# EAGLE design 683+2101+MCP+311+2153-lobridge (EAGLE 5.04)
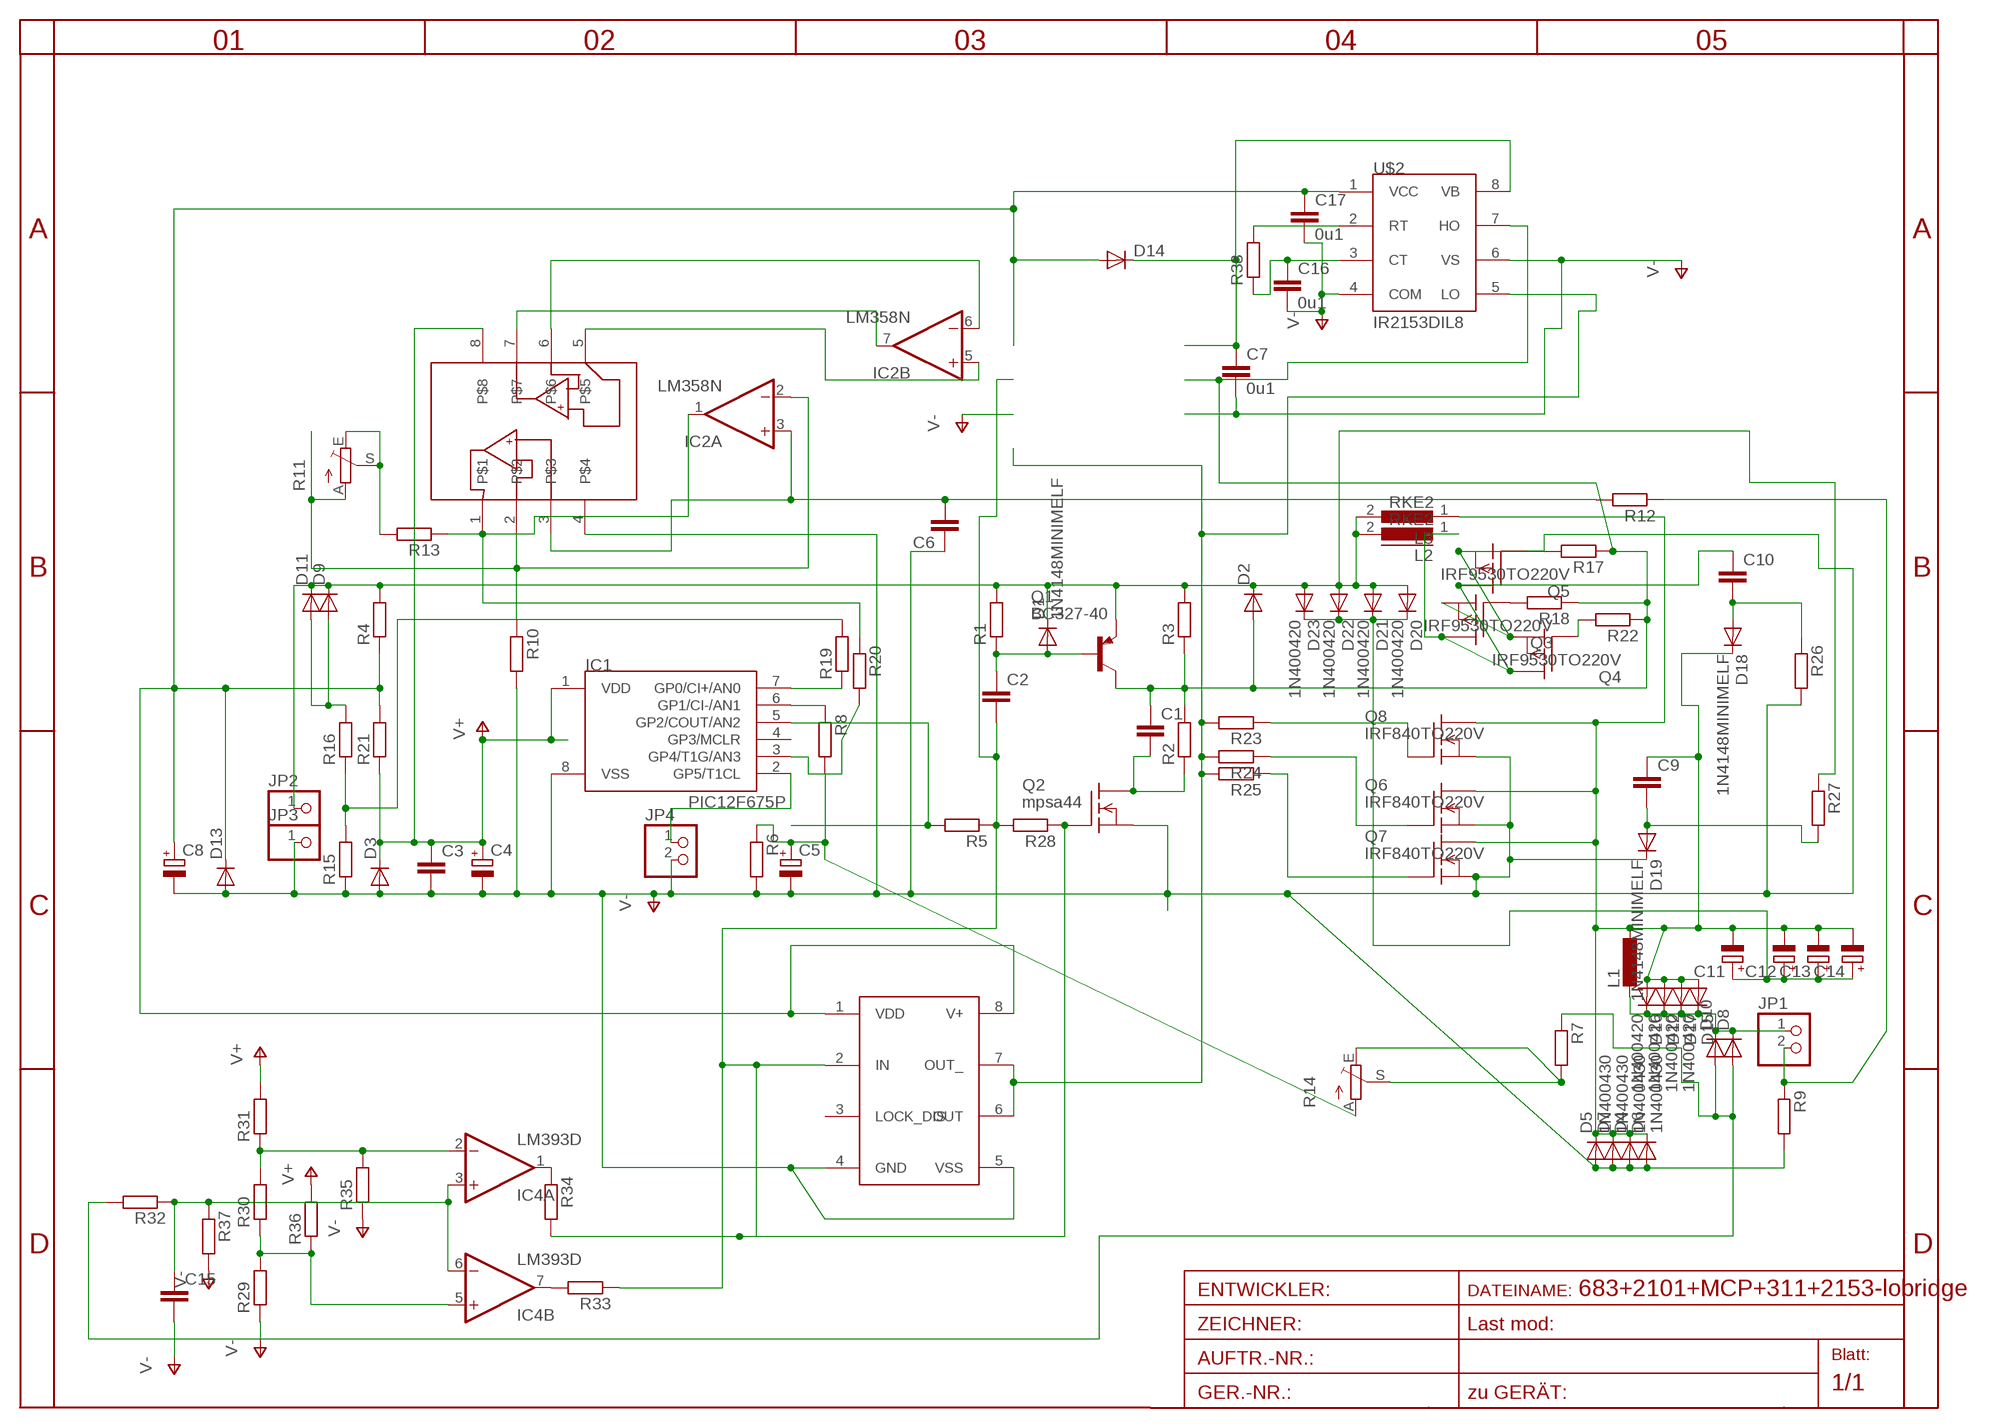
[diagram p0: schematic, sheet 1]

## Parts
C1  C-EU225-074X268  [C225-074X268]
C2  C-EU225-062X268  [C225-062X268]
C3  C-EU050-025X075  [C050-025X075]
C4  CPOL-EUE2.5-7  [E2,5-7]
C5  CPOL-EU5-13  [2,5-5-FLAT]
C6  C-EU025_050-025X075  [C025_050-025X075]
C7  0u1  C-EU050-025X075  [C050-025X075]
C8  CPOL-EU5-13  [2,5-5-FLAT]
C9  C-EUC1812  [C1812]
C10  C-EUC1812K  [C1812K]
C11  CPOL-EUSANYO_SMD_E7  [SANYO-OSCON_SMD_E7]
C12  CPOL-EUSANYO_SMD_E7  [SANYO-OSCON_SMD_E7]
C13  CPOL-EUSANYO_SMD_E7  [SANYO-OSCON_SMD_E7]
C14  CPOL-EUSANYO_SMD_E7  [SANYO-OSCON_SMD_E7]
C15  C-EU025-025X050  [C025-025X050]
C16  0u1  C-EU025-050X050  [C025-050X050]
C17  0u1  C-EU050-030X075  [C050-030X075]
D1  1N4148MINIMELF  [MINIMELF]
D2  DIODE-D-5  [D-5]
D3  DIODE-D-2.5  [D-2.5]
D4  1N400430  [DO41-30]
D5  1N400430  [DO41-30]
D6  1N400430  [DO41-30]
D7  1N400430  [DO41-30]
D8  DIODE-D-2.5  [D-2.5]
D9  DIODE-D-2.5  [D-2.5]
D10  DIODE-DO41-30  [DO41-30]
D11  DIODE-D-10  [D-10]
D12  1N400420  [DO41-20]
D13  DIODE-D-2.5  [D-2.5]
D14  DIODE-D-5  [D-5]
D15  1N400420  [DO41-20]
D16  1N400420  [DO41-20]
D17  1N400420  [DO41-20]
D18  1N4148MINIMELF  [MINIMELF]
D19  1N4148MINIMELF  [MINIMELF]
D20  1N400420  [DO41-20]
D21  1N400420  [DO41-20]
D22  1N400420  [DO41-20]
D23  1N400420  [DO41-20]
IC1  PIC12F675P  [DIL8]
IC2  LM358N  [DIL08]
IC3  TC4432X  [SO-08]
IC4  LM393D  [SO08]
JP1  PINHD-1X2  [1X02]
JP2  PINHD-1X1  [1X01]
JP3  PINHD-1X1  [1X01]
JP4  PINHD-1X2  [1X02]
L1  L-EU0204/7  [0204/7]
L2  RKE2  [RKE2]
L3  RKE2  [RKE2]
Q1  BC327-40  [TO92-EBC]
Q2  mpsa44  TN0604N3  [TO-92]
Q3  IRF9530TO220V  [TO220V]
Q4  IRF9530TO220V  [TO220V]
Q5  IRF9530TO220V  [TO220V]
Q6  IRF840TO220V  [TO220V]
Q7  IRF840TO220V  [TO220V]
Q8  IRF840TO220V  [TO220V]
R1  R-EU_0204/2V  [0204V]
R2  R-EU_0207/25  [0207/25]
R3  R-EU_0204/2V  [0204V]
R4  R-EU_0207/10  [0207/10]
R5  R-EU_0207/40  [0207/40]
R6  R-EU_0207/10  [0207/10]
R7  R-EU_0207/15  [0207/15]
R8  R-EU_0207/10  [0207/10]
R9  R-EU_0207/10  [0207/10]
R10  R-EU_0207/15  [0207/15]
R11  TRIM_EU-CIP20C-4MM  [CIP20C-4MM]
R12  R-EU_0207/30  [0207/30]
R13  R-EU_0207/40  [0207/40]
R14  TRIM_EU-CIP20C-4MM  [CIP20C-4MM]
R15  R-EU_0204/5  [0204/5]
R16  R-EU_0207/25  [0207/25]
R17  R-EU_R1206  [R1206]
R18  R-EU_R1206  [R1206]
R19  R-EU_0204/5  [0204/5]
R20  R-EU_0204/5  [0204/5]
R21  R-EU_0207/10  [0207/10]
R22  R-EU_R1206  [R1206]
R23  R-EU_R1206  [R1206]
R24  R-EU_R1206  [R1206]
R25  R-EU_R1206  [R1206]
R26  R-EU_0207/25  [0207/25]
R27  R-EU_0207/30  [0207/30]
R28  R-EU_R0805  [R0805]
R29  R-EU_0204/5  [0204/5]
R30  R-EU_0204/5  [0204/5]
R31  R-EU_0204/5  [0204/5]
R32  R-EU_0207/40  [0207/40]
R33  R-EU_0207/12  [0207/12]
R34  R-EU_0207/20  [0207/20]
R35  R-EU_0204/5  [0204/5]
R36  R-EU_0204/5  [0204/5]
R37  R-EU_0204/5  [0204/5]
R38  R-EU_0204/2V  [0204V]
U$1  MCP6042SOIC  [SO-08]
U$2  IR2153DIL8  [DIL08]

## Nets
BB: C2.2 IC3.2(IN) Q2.2(G) R5.1 R28.1 R28.2 R33.1 R34.2
CT: C16.1 R38.1 U$2.3(CT)
DRAIN: C9.1 C11.- C12.- C13.- C14.- D4.C D5.C D6.C D7.C D12.A D15.A D16.A D17.A D18.C L1.1 L3.1 Q6.2(D) Q7.2(D) Q8.2(D)
GATE: C1.1 D2.A Q1.C R2.2 R3.1 R17.1 R18.1 R22.1 U$2.7(HO)
MPOINT: C5.+ R6.1 R8.2 R14.A
N$1: C1.2 Q2.3(D) R2.1
N$2: IC2.6(B:-IN) U$1.6
N$3: IC1.5(GP2/COUT/AN2) R5.2
N$4: Q3.1(G) R18.2
N$5: IC1.6(GP1/CI-/AN1) R8.1
N$6: IC2.2(A:-IN) R10.1 R11.A U$1.2
N$7: IC2.1(A:OUT) R13.1 R20.1 U$1.1
N$9: C6.2 IC2.3(A:+IN) R12.2 U$1.3
N$10: R7.2 R14.E R14.S
N$11: Q5.1(G) R17.2
N$12: R15.2 R16.1 R19.2
N$13: D9.A D11.A R16.2
N$14: IC1.7(GP0/CI+/AN0) R19.1
N$15: IC1.2(GP5/T1CL) JP4.1
N$16: D8.A D10.A R7.1 R32.2
N$17: IC1.3(GP4/T1G/AN3) R20.2
N$18: IC2.5(B:+IN) U$1.5
N$19: C15.1 IC4.3(A:+IN) IC4.6(B:-IN) R32.1 R37.1
N$20: IC2.7(B:OUT) U$1.7
N$21: C10.1 L2.1 Q3.2(D) Q4.2(D) Q5.2(D)
N$22: IC4.7(B:OUT) R33.2
N$23: Q4.1(G) R22.2
N$24: C10.2 D18.A R26.1
N$25: Q7.1(G) R25.1
N$26: Q6.1(G) R24.1
N$27: Q8.1(G) R23.1
N$28: C9.2 D19.A R27.2
N$29: R11.E R11.S R13.2
N$30: IC4.1(A:OUT) R34.1
N$31: C11.+ C12.+ C13.+ C14.+ D20.C D21.C D22.C D23.C
N$32: IC4.5(B:+IN) R29.2 R30.1 R36.1
N$33: IC3.6(OUT) IC3.7(OUT_) R23.2 R24.2 R25.2 U$2.5(LO)
N$34: IC4.2(A:-IN) R30.2 R31.1 R35.2
N$40: R38.2 U$2.2(RT)
OUT+: D8.C D10.C D12.C D15.C D16.C D17.C JP1.1 L1.2
OUT-: JP1.2 R9.1 R12.1
TB: C2.1 D1.A Q1.B R1.1
V+: C3.1 C4.+ D3.C IC1.1(VDD) R21.1 R31.2 R36.2 U$1.8
V-: C3.2 C4.- C5.- C6.1 C7.2 C8.- C15.2 C16.2 C17.2 D3.A D4.A D5.A D6.A D7.A D13.A D19.C IC1.8(VSS) IC3.4(GND) IC3.5(VSS) JP3.1 JP4.2 Q2.1(S) Q3.3(S) Q4.3(S) Q5.3(S) Q6.3(S) Q7.3(S) Q8.3(S) R6.2 R9.2 R10.2 R15.1 R26.2 R29.1 R35.1 R37.2 U$1.4 U$2.4(COM) U$2.6(VS)
VB: C7.1 D14.C U$2.8(VB)
VCC: C8.+ C17.1 D13.C D14.A IC3.1(VDD) IC3.8(V+) R4.1 R21.2 U$2.1(VCC)
VIN: D1.C D2.C D9.C D11.C D20.A D21.A D22.A D23.A JP2.1 L2.2 L3.2 Q1.E R1.2 R3.2 R4.2 R27.1
Unconnected: IC1.4(GP3/MCLR) IC3.3(LOCK_DIS)

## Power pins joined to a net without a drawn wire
V+: IC2.8(P:V+) IC4.8(P:V+)
V-: IC2.4(P:V-) IC4.4(P:V-)

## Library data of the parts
C1-C3 C6 C7 C9 C10 C15-C17 = rcl-2:C-EU: CAPACITOR, European symbol
C4 C5 C8 C11-C14 = rcl-2:CPOL-EU: POLARIZED CAPACITOR, European symbol
D1 D18 D19 = diode-1:1N4148: DIODE
D2 D3 D8-D11 D13 D14 = diode-1:DIODE-: DIODE
D4-D7 D12 D15-D17 D20-D23 = diode-1:1N4004: DIODE
IC1 = microchip-5:PIC12F6*: uPC nW 1k Program Flash memory 2x Timer Comparator 10b A/D converter/ 4xIN
IC2 = linear:LM358: OP AMP also LM158; LM258; LM2904 Source: http://cache.national.com/ds/LM/LM158.pdf
IC3 = microchip:TC4432
IC4 = linear:LM393: COMPARATOR
JP1 JP4 = pinhead:PINHD-1X2: PIN HEADER
JP2 JP3 = pinhead:PINHD-1X1: PIN HEADER
L1 = rcl-2:L-EU: INDUCTOR, European symbol
L2 L3 = inductors:RKE2: INDUCTOR
Q1 = transistor-pnp:BC327*: PNP Transistror
Q2 = transistor-fet:TN0604N3: N-Channel Enhancement MOSFET 40V; 4A; 0,75Ohm
Q3-Q5 = transistor-fet:IRF9530: P-Channel Enhancement MOSFET (HEXFET); -100V; -12A; 0,3Ohm
Q6-Q8 = transistor-fet:IRF840: N-Channel Enhancement MOSFET (HEXFET); 500V; 8A; 0,85Ohm
R1-R10 R12 R13 R15-R38 = rcl-2:R-EU_: RESISTOR, European symbol
R11 R14 = pot:TRIM_EU-: POTENTIOMETER
U$1 = microchip-3:MCP6042
U$2 = irf-2:IR2153

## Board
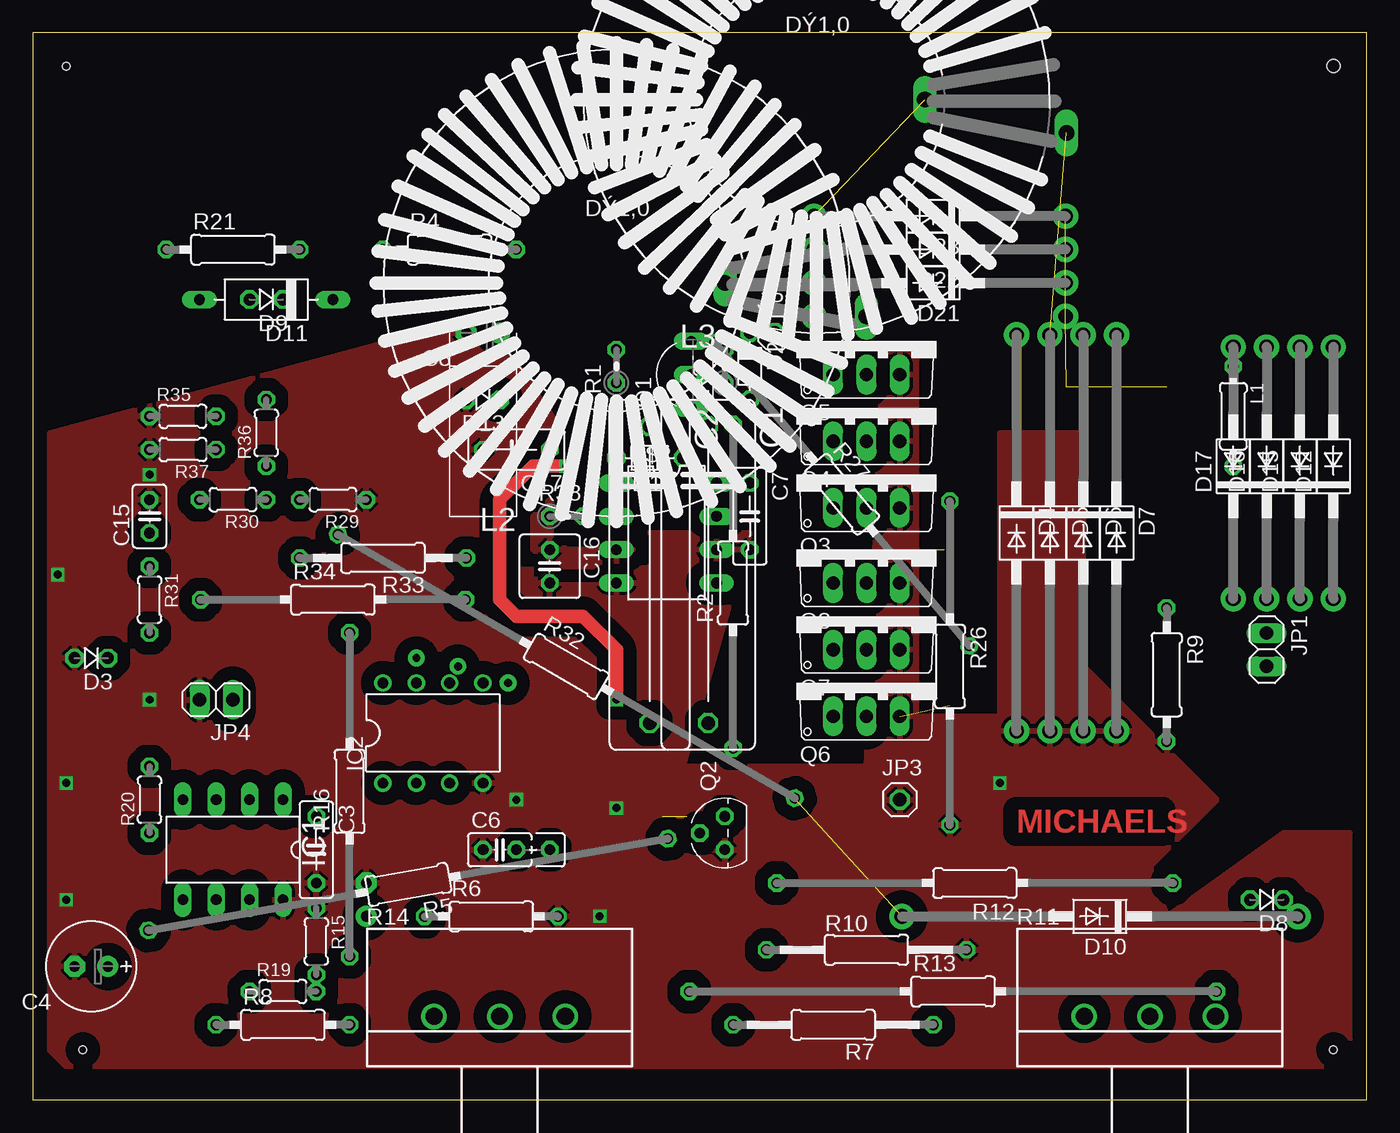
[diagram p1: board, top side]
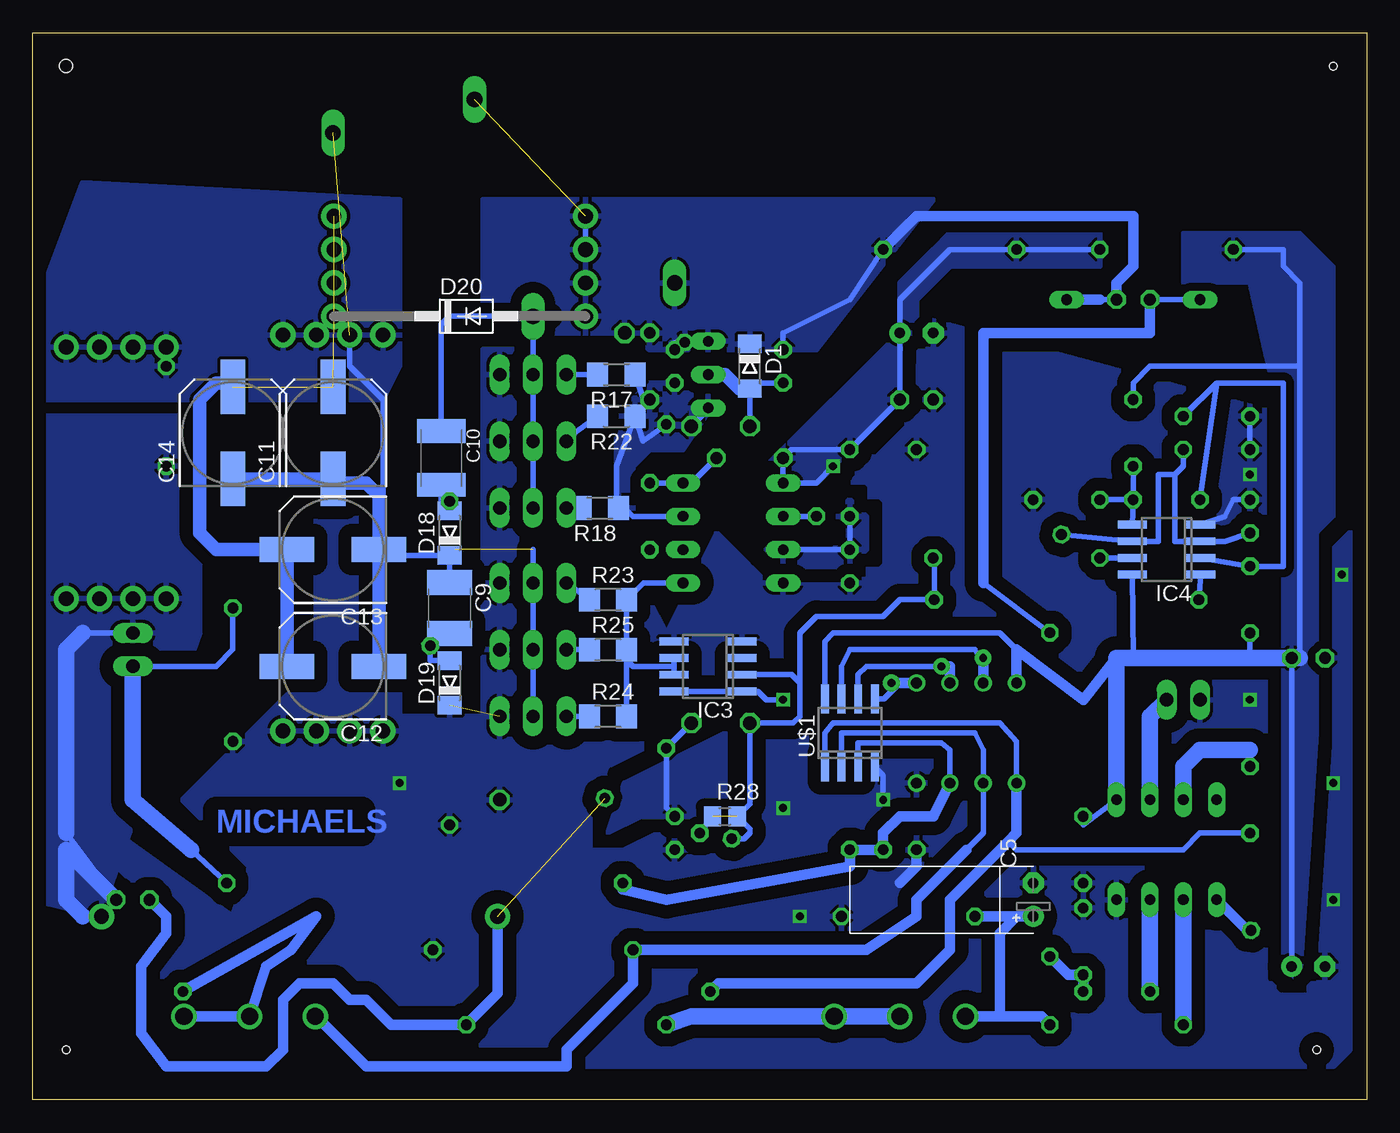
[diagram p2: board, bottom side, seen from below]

Size 101.6 x 81.28 mm. Coordinates in mm from the lower left corner, seen from the top.
Outline: 0,0 101.6,0 101.6,81.28 0,81.28 0,0
Copper layers (1*16): Top 0.035mm / dielectric 1.5mm / Bottom 0.035mm
Design rules "default": minimum track width 10mil, minimum drill 24mil, track to track 8mil, track to pad 8mil, pad to pad 8mil, via to via 8mil, smd to smd 8mil, copper to edge 40mil, drill to drill 8mil, minimum pad ring 10mil, minimum via ring 8mil, stop-mask expansion 4mil, vias tented up to drill 0mil, thermal gap 10mil
Holes 0.6 mm at 2.54,78.74 3.81,3.81 99.06,3.81
Holes 1 mm at 99.06,78.74

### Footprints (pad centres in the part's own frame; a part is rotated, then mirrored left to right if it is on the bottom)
C225-074X268 = drill 1.016 octagon: 1 -11.303,0; 2 11.303,0
C225-062X268 = drill 1.016 octagon: 1 -11.303,0; 2 11.303,0
C050-025X075 = drill 0.813 octagon: 1 -2.54,0; 2 2.54,0
E2,5-7 = drill 0.813 pad 1.6 round: + -1.27,0 | drill 0.813 pad 1.6 octagon: - 1.27,0
2,5-5-FLAT = drill 0.813 pad 1.6 round: + -1.27,0 | drill 0.813 pad 1.6 octagon: - 1.27,0
C025_050-025X075 = drill 0.813 octagon: 1 -1.27,0; 2 1.27,0; 3 3.81,0
C1812 = smd 1.9 x 3.4: 1 -1.95,0; 2 1.95,0
C1812K = smd 1.8 x 3.7: 1 -2.05,0; 2 2.05,0
SANYO-OSCON_SMD_E7 = smd 4.15 x 1.9: + 3.5,0; - -3.5,0
C025-025X050 = drill 0.813 octagon: 1 -1.27,0; 2 1.27,0
C025-050X050 = drill 0.813 octagon: 1 -1.27,0; 2 1.27,0
C050-030X075 = drill 0.813 octagon: 1 -2.54,0; 2 2.54,0
MINIMELF = smd 1.4 x 1.8: A 1.7,0; C -1.7,0
D-5 = drill 0.9 octagon: A 2.54,0; C -2.54,0
D-2.5 = drill 0.9 octagon: A 1.27,0; C -1.27,0
DO41-30 = drill 1.118 pad 1.93 round: A 15.08,0; C -15.08,0
D-10 = drill 0.813 long: A 5.08,0; C -5.08,0
DO41-20 = drill 1.118 pad 1.93 round: A 9.08,0; C -10.08,0
DIL8 = drill 0.813 long: 1 -3.81,-3.81; 2 -1.27,-3.81; 3 1.27,-3.81; 4 3.81,-3.81; 5 3.81,3.81; 6 1.27,3.81; 7 -1.27,3.81; 8 -3.81,3.81
DIL08 = drill 0.813 pad 1.27 round: 1 -3.81,-3.81; 2 -1.27,-3.81; 3 1.27,-3.81; 4 3.81,-3.81; 5 3.81,3.81; 6 1.27,3.81; 7 -1.27,3.81; 8 -3.81,3.81
SO-08 = smd 0.6 x 2.2: 1 -1.905,-2.6; 2 -0.635,-2.6; 3 0.635,-2.6; 4 1.905,-2.6; 5 1.905,2.6; 6 0.635,2.6; 7 -0.635,2.6; 8 -1.905,2.6
SO08 = smd 0.6 x 2.2: 1 -1.905,-2.6; 2 -0.635,-2.6; 3 0.635,-2.6; 4 1.905,-2.6; 5 1.905,2.6; 6 0.635,2.6; 7 -0.635,2.6; 8 -1.905,2.6
1X02 = drill 1.016 long: 1 -1.27,0; 2 1.27,0
1X01 = drill 1.016 octagon: 1 0,0
0204/7 = drill 0.813 octagon: 1 -3.81,0; 2 3.81,0
RKE2 = drill 1.194 long: 1 -19.05,2.54; 2 -8.255,0
TO92-EBC = drill 0.813 long: B 0,-1.27; C -2.54,-1.27; E 2.54,-1.27
TO-92 = drill 0.813 octagon: 1 -1.27,0; 2 0,1.905; 3 1.27,0
TO220V = drill 1.016 long: 1 -2.54,-2.54; 2 0,-2.54; 3 2.54,-2.54
0204V = drill 0.813 octagon: 1 -1.27,0; 2 1.27,0
0207/25 = drill 0.813 octagon: 1 -12.58,0; 2 12.08,0
0207/10 = drill 0.813 octagon: 1 -5.08,0; 2 5.08,0
0207/40 = drill 0.813 octagon: 1 -20.08,0; 2 20.08,0
0207/15 = drill 0.813 octagon: 1 -7.62,0; 2 7.62,0
CIP20C-4MM = drill 1.3 pad 1.93 round: A -5,0; E 5,0; S 0,0
0207/30 = drill 0.813 octagon: 1 -15.08,0; 2 15.08,0
0204/5 = drill 0.813 octagon: 1 -2.54,0; 2 2.54,0
R1206 = smd 1.6 x 1.803: 1 -1.422,0; 2 1.422,0
R0805 = smd 1.3 x 1.5: 1 -0.95,0; 2 0.95,0
0207/12 = drill 0.813 octagon: 1 -6.35,0; 2 6.35,0
0207/20 = drill 0.813 octagon: 1 -10.08,0; 2 10.08,0
DIL08' = drill 0.813 long: 1 -3.81,-3.81; 2 -1.27,-3.81; 3 1.27,-3.81; 4 3.81,-3.81; 5 3.81,3.81; 6 1.27,3.81; 7 -1.27,3.81; 8 -3.81,3.81

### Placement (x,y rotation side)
C1  51.44,40.01 270 top
C2  46.99,40.01 270 top
C3  21.59,19.05 270 top
C4  4.45,10.16 180 top
C5  25.4,15.24 90 bottom
C6  35.56,19.05 0 top
C7  54.61,44.45 270 top
C8  34.29,58.42 180 top
C9  69.85,37.47 270 bottom
C10  70.48,48.9 270 bottom
C11  78.74,50.8 90 bottom
C12  78.74,33.02 180 bottom
C13  78.74,41.91 180 bottom
C14  86.36,50.8 90 bottom
C15  8.89,44.45 90 top
C16  39.37,40.64 270 top
C17  36.83,49.53 180 top
D1  46.99,55.88 270 bottom
D2  54.61,55.88 270 top
D3  4.45,33.66 180 top
D4  74.93,43.18 270 top
D5  77.47,43.18 270 top
D6  80.01,43.18 270 top
D7  82.55,43.18 270 top
D8  93.98,15.24 180 top
D9  17.78,60.96 180 top
D10  81.28,13.97 180 top
D11  17.78,60.96 180 top
D12  99.06,48.26 90 top
D13  34.29,53.34 180 top
D14  46.99,48.9 180 top
D15  96.52,48.26 90 top
D16  93.98,48.26 90 top
D17  91.44,48.26 90 top
D18  69.85,43.18 90 bottom
D19  69.85,31.75 90 bottom
D20  68.58,59.69 0 bottom
D21  68.58,62.23 180 top
D22  68.58,64.77 180 top
D23  68.58,67.31 180 top
IC1  15.24,19.05 180 top
IC2  30.48,27.94 0 top
IC3  50.16,33.02 90 bottom
IC4  15.24,41.91 90 bottom
JP1  93.98,34.29 270 top
JP2  56.52,58.42 0 top
JP3  66.04,22.86 0 top
JP4  13.97,30.48 180 top
L1  91.44,52.07 270 top
L2  44.45,62.23 180 top
L3  59.69,76.2 180 top
Q1  48.9,55.24 90 top
Q2  52.7,20.32 90 top
Q3  63.5,47.62 0 top
Q4  63.5,52.7 0 top
Q5  63.5,57.78 0 top
Q6  63.5,31.75 0 top
Q7  63.5,36.83 0 top
Q8  63.5,41.91 0 top
R1  44.45,55.88 90 top
R2  53.34,39.37 90 top
R3  52.7,55.88 90 top
R4  31.75,64.77 0 top
R5  28.58,16.4 190 top
R6  34.92,13.97 0 top
R7  60.96,5.71 180 top
R8  19.05,5.71 0 top
R9  86.36,32.38 270 top
R10  63.5,11.43 0 top
R11  85.09,6.35 0 top
R12  71.75,16.51 180 top
R13  70.09,8.26 0 top
R14  35.56,6.35 0 top
R15  21.59,12.06 270 top
R16  24.13,23.5 90 top
R17  57.15,55.24 180 bottom
R18  58.42,45.09 180 bottom
R19  19.05,8.26 0 top
R20  8.89,22.86 90 top
R21  15.24,64.77 0 top
R22  57.15,52.07 180 bottom
R23  57.78,38.1 0 bottom
R24  57.78,29.21 0 bottom
R25  57.78,34.29 0 bottom
R26  69.85,33.02 270 top
R27  61.63,46.14 310 top
R28  48.9,21.59 0 bottom
R29  22.86,45.72 180 top
R30  15.24,45.72 180 top
R31  8.89,38.1 270 top
R32  40.64,33.02 330 top
R33  26.67,41.27 180 top
R34  22.86,38.1 0 top
R35  11.43,52.07 0 top
R36  17.78,50.8 90 top
R37  11.43,49.53 180 top
R38  40.64,44.45 0 top
U$1  39.37,27.94 0 bottom
U$2  IR2153DIL8  [DIL08']  48.26,43.18 270 top

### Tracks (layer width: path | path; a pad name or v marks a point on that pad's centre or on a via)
BB  (1 unrouted)
  Bottom 0.406: R5.1 47.42,19.89 46.99,20.32 46.99,20.64 R28.2 46.99,22.55 C2.2 43.69,28.7 43.18,29.21 43.18,31.75 | R28.1 Q2.2 | 43.18,31.75 43.81,32.38 IC3.2 | 43.18,31.75 43.18,35.56 41.91,36.83 36.83,36.83 35.56,38.1 R34.2 32.94,41.2 R33.1
CT
  Bottom 0.406: R38.1 C16.1 U$2.3
  pour Bottom (isolate 0.813, rank 3): 45.72,41.91 40.64,41.91 39.37,43.18 40.64,44.45 39.37,45.72 38.1,44.45 38.1,41.91 39.37,40.64 44.45,40.64
  pour Top (isolate 0.813, rank 3): 45.72,41.91 40.64,41.91 39.37,43.18 40.64,44.45 39.37,45.72 38.1,44.45 38.1,41.91 39.37,40.64 44.45,40.64
DRAIN  (2 unrouted)
  Bottom 0.406: D18.C C9.1 | Q6.2 Q7.2 Q8.2 63.5,41.91 | D18.C 69.42,41.91 | D18.C 74.5,41.48 74.93,41.91 C13.- | D5.C 77.47,55.88 74.93,53.34 74.93,43.49 75.24,43.18
  Bottom 1.016: C12.- C13.- 75.24,43.18 75.24,46.03 76.2,46.99 78.43,46.99 C11.- 86.05,47.3 86.36,46.99 C14.-
  pour Bottom (isolate 0.254, rank 5): 101.6,53.34 74.93,53.34 73.66,55.88 73.66,68.58 97.79,69.85 101.6,59.69
GATE
  Bottom 0.406: R18.1 57.15,45.09 57.15,45.72 | 57.15,45.72 57.15,48.26 R22.1 55.11,50.18 R2.2 | D2.A 55.09,53.34 R17.1 | U$2.7 55.88,44.45 57.15,45.72 | Q1.C 50.16,52.58 C1.1
  pour Bottom (isolate 0.813, rank 2): 49.53,53.34 50.8,54.61 53.34,54.61 54.61,54.61 57.15,52.07 57.15,44.45 55.88,44.45 55.88,48.26 54.61,49.53 52.07,49.53
MPOINT
  Bottom 0.813: R6.1 C5.+ 26.67,13.97 27.94,12.7 27.94,6.35 | 27.94,6.35 24.77,6.35 R8.2 | 27.94,6.35 R14.A
N$1
  Bottom 0.406: C1.2 R2.1 53.34,22.23 Q2.3
  pour Bottom (isolate 0.61, rank 3): 48.9,27.94 56.52,24.13 57.78,20.32 55.24,21.59 48.9,21.59
N$2  (via drill 0.6 pad 1.27)
  Bottom 0.406: U$1.6 38.73,32.38 38.1,33.02 v32.38,33.02 31.75,33.02
  Bottom 0.813: IC2.6 31.75,33.02
N$3
  Bottom 0.813: R5.2 9.1,12.91 IC1.5
N$4
  Bottom 0.406: R18.2 Q3.1
N$5
  Bottom 1.27: R8.1 IC1.6
N$6
  Bottom 0.406: 30.48,19.05 29.21,20.32 IC2.2 29.21,26.67 29.84,27.94 40.01,27.94 U$1.2
  Bottom 0.813: 30.48,19.05 34.29,15.24 34.29,13.97 38.1,11.43 R10.1 55.88,8.89 60.96,3.81 60.96,2.54 76.2,2.54 80.01,6.35 R11.A
N$7
  Bottom 0.406: U$1.1 41.27,27.94 40.64,28.7 27.94,28.7 26.67,27.3 IC2.1 | R20.1 12.7,20.32 13.97,19.05 26.67,19.05 27.3,19.68
  Bottom 0.813: IC2.1 26.67,20.32 27.3,19.68 31.75,15.24 31.75,11.43 34.29,8.89 49.38,8.89 R13.1
N$8  (via drill 0.6 pad 1.27)
  other vias: 36.2,31.75
N$9
  Bottom 0.406: U$1.3 38.73,27.18 32.38,27.18 31.75,26.67 IC2.3
  Bottom 0.813: R12.2 56.67,16.04 53.34,15.24 39.37,17.78 39.37,19.05 C6.2 36.83,20.32 35.56,21.59 33.02,21.59 IC2.3
N$10
  Bottom 1.27: R14.S R14.E 51.44,6.35 R7.2
N$11
  Bottom 0.406: R17.2 Q5.1
N$12
  Bottom 0.813: R19.2 R15.2 22.74,9.53 R16.1
N$13
  Bottom 0.406: D9.A D11.A | R16.2 29.2,39.37
  Bottom 0.813: D9.A 16.51,58.42 29.21,58.42 29.21,43.18 29.2,39.37
N$14
  Bottom 1.27: R19.1 IC1.7
N$15
  Bottom 1.27: IC1.2 16.51,29.21 JP4.1
N$16  (1 unrouted)
  Bottom 0.813: D8.A 91.44,13.97 91.44,12.7 93.34,10.16 93.34,5.08 91.44,2.54 83.82,2.54 82.55,3.81 82.55,7.62 81.28,8.89 78.74,8.89 77.47,7.62 76.2,7.62 74.3,5.71 R7.1 66.2,8.1 D10.A
N$17
  Bottom 0.406: R20.2 8.89,26.67
  Bottom 1.27: 8.89,26.67 12.7,26.67 13.97,25.4 IC1.3
N$18
  Bottom 0.406: U$1.5 36.77,30.54 35.56,31.75
  Bottom 0.813: IC2.5 35.56,31.75
N$19
  Bottom 0.406: C15.1 10.79,42.55 IC4.3 14.61,42.55 14.61,47.62 | R32.1 IC4.6 15.88,42.55 15.88,47.62 14.61,47.62 | R37.1 13.97,48.26 14.61,47.62
N$20
  Bottom 0.406: U$1.7 40.01,33.02 39.37,34.29 29.84,34.29 29.21,33.02
  Bottom 0.813: IC2.7 29.21,33.02
N$21
  Bottom 0.406: L2.1 Q5.2 Q4.2 Q3.2 | C10.1 70.48,59.05 69.85,59.69 L2.1 | L2.1 62.23,59.69
N$22
  Bottom 0.406: IC4.7 R33.2
N$23
  Bottom 0.406: R22.2 60.33,50.8 Q4.1
N$24
  Bottom 0.406: D18.A R26.1 70.48,45.6 C10.2
N$25
  Bottom 0.406: R25.1 Q7.1
N$26
  Bottom 0.406: R24.1 Q6.1
N$27
  Bottom 0.406: R23.1 Q8.1
N$28
  Bottom 0.406: C9.2 71.33,35.52 R27.2 71.33,33.45 D19.A
N$29
  Bottom 0.813: R13.2 80.01,13.97 81.92,11.43 83.82,10.16 R11.S R11.E
N$30
  Bottom 0.406: IC4.1 R34.1
N$31  (5 unrouted)
  Bottom 1.016: C12.+ C13.+ 87.63,41.91 88.9,43.18 88.9,53.34 87.63,54.61 86.67,54.61 C14.+
N$32
  Bottom 0.406: IC4.5 R30.1 | R30.1 R29.2 | R30.1 R36.1
N$33
  Bottom 0.406: IC3.7 52.77,33.02 | 52.77,33.02 IC3.6 | U$2.5 55.09,39.37 R23.2 R25.2 56.36,33.5 | 56.36,33.5 55.88,33.02 52.77,33.02 | 56.36,33.5 R24.2
N$34
  Bottom 0.406: 11.43,54.61 R30.2 | 11.43,54.61 6.35,54.61 6.35,40.64 R31.1 IC4.2 | 11.43,54.61 R35.2
N$35  (via drill 0.6 pad 1.27)
  other vias: 29.21,33.66
N$40
  Bottom 0.406: R38.2 U$2.2
OUT+
  Bottom 0.406: 97.79,35.56 JP1.1 | D8.C 99.06,20.32 | D10.C 97.79,13.97
  Bottom 1.27: 97.79,35.56 99.06,34.29 99.06,20.32 | D8.C 99.06,19.05 99.06,15.24 97.79,13.97
  pour Bottom (isolate 1.016, rank 5): 88.9,52.07 101.6,52.07 101.6,15.24 96.52,13.97 88.9,35.56
OUT-
  Bottom 0.406: R12.1 89.53,19.05 | JP1.2 87.63,33.02 86.36,34.29 R9.1
  Bottom 1.27: 89.53,19.05 93.98,22.86 JP1.2
TB
  Bottom 0.406: R1.1 46.56,54.61 D1.A C2.1
  Bottom 1.016: D1.A 47.83,54.18 48.9,55.24 Q1.B
V+
  Bottom 0.406: R21.1 6.35,64.77 6.35,63.5 5.08,62.23 5.08,55.88 | 5.08,34.29 5.08,55.88 | 5.08,34.29 D3.C C4.+ | 5.08,34.29 5.08,33.66 | IC1.1 21.59,20.95 C3.1 | U$1.8 41.27,34.92 40.64,35.56 27.94,35.56 26.67,34.29 | 17.78,33.66 IC4.8 | 8.89,33.66 R31.2 | R36.2 17.78,54.61 16.51,55.88 5.08,55.88
  Bottom 0.813: 19.05,33.66 21.59,30.48 26.67,34.29 IC2.8
  Bottom 1.27: 5.08,33.66 D3.C 8.89,33.66 17.78,33.66 19.05,33.66 IC1.1
  pour Bottom (isolate 0.61, rank 3): 13.97,66.04 5.08,66.04 2.54,63.5 2.54,44.45 3.81,43.18 3.81,27.94 5.08,8.89 6.35,10.16 6.35,50.8 8.89,62.23 13.97,62.23
V-  (via drill 0.6)  (1 unrouted)
  Bottom 0.406: IC4.4 10.79,44.45 10.16,45.72 C15.2 | v36.83,22.86 36.83,24.7 U$1.4 | R37.2 R35.1
  Bottom 0.813: C6.1 34.29,17.78 35.56,16.51
  other vias: 44.45,22.23 43.18,13.97 73.66,24.13 8.89,30.48 8.89,47.62 1.91,40.01 2.54,24.13 2.54,15.24
  pour Top (isolate 1.016, rank 5): 1.27,50.8 34.29,59.69 45.72,43.18 54.61,43.18 49.53,25.4 63.5,25.4 64.77,57.15 67.31,57.15 67.31,29.21 73.66,29.21 73.66,50.8 80.01,50.8 80.01,33.02 90.17,22.86 85.09,17.78 86.36,13.97 95.25,20.32 100.33,20.32 100.33,3.81 99.06,2.54 2.54,2.54 1.27,3.81
  pour Bottom (isolate 1.016, rank 5): 1.27,50.8 34.29,59.69 45.72,39.37 49.53,43.18 53.34,35.56 64.77,57.15 67.31,57.15 67.31,29.21 73.66,29.21 73.66,50.8 80.01,50.8 80.01,33.02 90.17,22.86 85.09,17.78 86.36,13.97 95.25,20.32 100.33,20.32 100.33,3.81 99.06,2.54 2.54,2.54 1.27,3.81
VB
  Bottom 0.406: C7.1 U$2.8 51.44,46.99 D14.C
VCC  (via drill 0.6)
  Top 1.016: v40.64,48.26 38.1,48.26 35.56,45.72 35.56,38.1 36.83,36.83 41.91,36.83 44.45,34.29 v44.45,30.48
  Bottom 0.406: IC3.8 IC3.1 46.35,31.11 45.72,30.48 v44.45,30.48 | R21.2 R4.1 31.75,64.77 35.56,60.96 C8.+ D13.C C17.1 43.81,49.53 D14.A U$2.1 41.91,46.99 v40.64,48.26
  pour Bottom (isolate 0.813, rank 2): 20.32,66.04 31.75,66.04 33.02,64.77 35.56,62.23 35.56,58.42 45.72,48.26 44.45,46.99 41.91,46.99 35.56,53.34 35.56,57.15 34.29,58.42 34.29,60.96 31.75,63.5 20.32,63.5
VIN  (1 unrouted)
  Bottom 0.406: D9.C 20.32,60.96 | R4.2 39.37,60.96 44.45,58.42 R1.2 | R27.1 52.7,57.69 R3.2 | D22.A D23.A
  Bottom 0.813: 20.32,60.96 D11.C | R4.2 34.29,67.31 17.78,67.31 17.78,63.5 19.05,62.23 D9.C
  pour Bottom (isolate 0.813, rank 2): 33.02,68.58 67.31,68.58 67.31,58.42 55.88,58.42 54.61,57.15 41.91,57.15

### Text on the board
Top: MICHAELS
Bottom: MICHAELS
